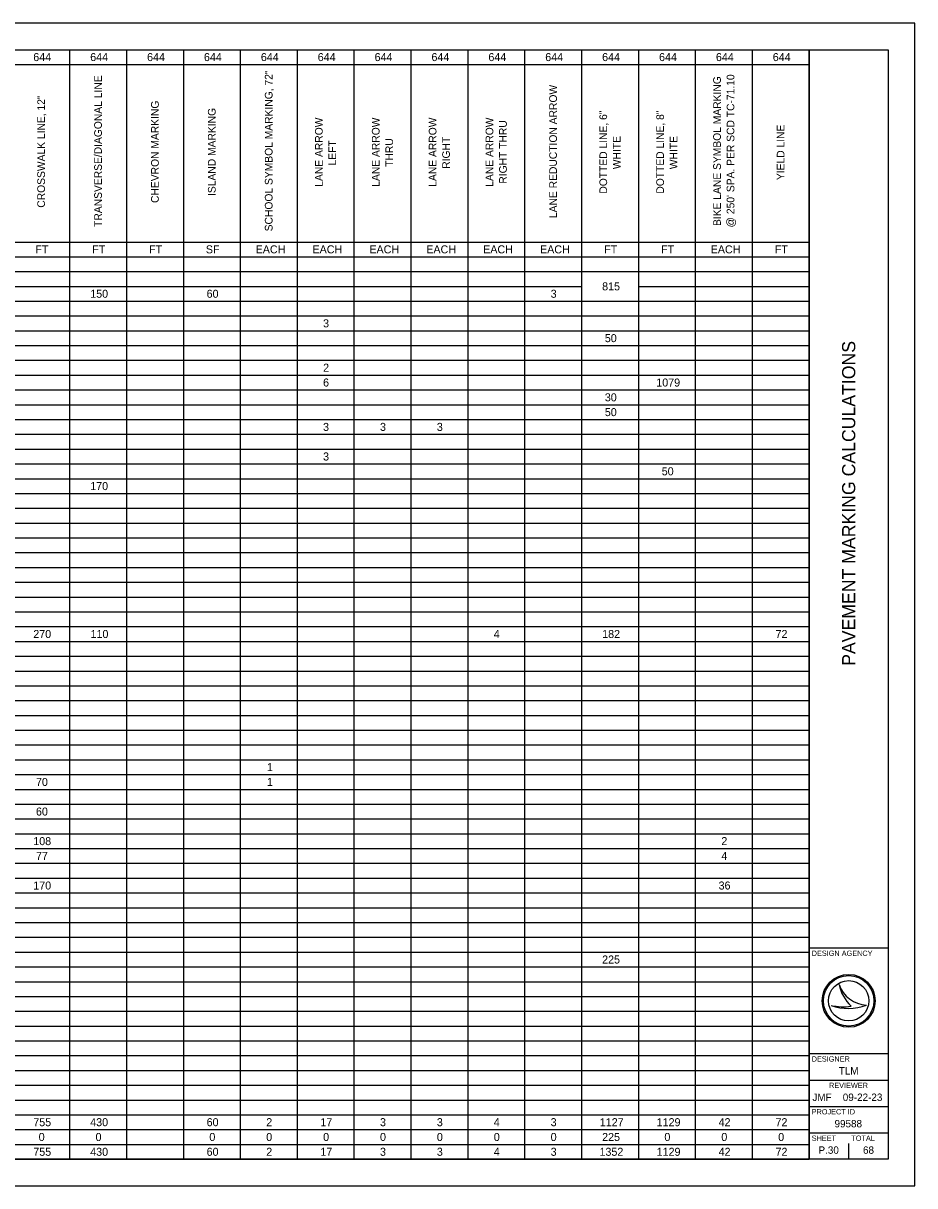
# Model space of a CAD drawing. Extents: x 0 to 34, y 0 to 22.
# Drawn here: x 17.13 to 34, y 0 to 22 of the extents above; entities that cross this region are included whole.
import ezdxf

# ---------------------------------------------------------------- set-up
doc = ezdxf.new("R2010")
doc.units = 0
for name, color, linetype in [('SH_Border', 7, 'Continuous'), ('SH_Cut_Line', 7, 'Continuous'), ('SH_Data', 7, 'Continuous'), ('SH_Text', 7, 'Continuous')]:
    doc.layers.add(name, color=color, linetype=linetype)

msp = doc.modelspace()

# ---------------------------------------------------------------- linework, layer by layer
at = {"layer": 'SH_Border'}
for p, q in [((32, 0.5), (32, 21.5)), ((32, 4.5), (33.5, 4.5)), ((32, 2.5), (33.5, 2.5)), ((32, 2), (33.5, 2)), ((32, 1.5), (33.5, 1.5)), ((32, 1), (33.5, 1))]:
    msp.add_line(p, q, dxfattribs=at)
msp.add_lwpolyline([(1.5, 21.5), (33.5, 21.5), (33.5, 0.5), (1.5, 0.5)], close=True, dxfattribs=at)
at = {"layer": 'SH_Cut_Line'}
msp.add_lwpolyline([(0, 0), (34, 0), (34, 22), (0, 22)], close=True, dxfattribs=at)
at = {"layer": 'SH_Data'}
for p, q in [((32.567, 3.81), (32.567, 3.81)), ((32.417, 3.41), (32.417, 3.41)), ((32.75, 3.5), (32.75, 3.5)), ((33.087, 3.419), (33.087, 3.419)), ((32.375, 0.675), (32.375, 0.675)), ((32.75, 0.5), (32.75, 0.8))]:
    msp.add_line(p, q, dxfattribs=at)
for radius in [0.5, 0.477, 0.477, 0.382]:
    msp.add_circle((32.75, 3.5), radius, dxfattribs=at)
for centre, radius, start, end in [((33.116, 3.998), 0.58, 198.9257, 198.9319), ((33.347, 3.97), 0.796, 191.6379, 191.6421), ((33.116, 3.998), 0.58, 198.9319, 267.1657), ((33.347, 3.97), 0.796, 191.6421, 226.0947), ((32.739, 4.37), 1.013, 251.4576, 290.0832), ((32.648, 4.654), 1.266, 259.4964, 259.4995), ((32.739, 4.37), 1.013, 251.4527, 251.4576), ((32.648, 4.654), 1.266, 259.4995, 276.6672)]:
    msp.add_arc(centre, radius, start, end, dxfattribs=at)
at = {"layer": 'SH_Text'}
for p, q in [((1.5, 21.5), (32.001, 21.5)), ((18.009, 21.5), (18.009, 0.502)), ((19.085, 21.5), (19.085, 0.502)), ((20.161, 21.5), (20.161, 0.502)), ((21.238, 21.5), (21.238, 0.502)), ((22.314, 21.5), (22.314, 0.502)), ((23.39, 21.5), (23.39, 0.502)), ((24.467, 21.5), (24.467, 0.502)), ((25.543, 21.5), (25.543, 0.502)), ((26.619, 21.5), (26.619, 0.502)), ((27.696, 21.5), (27.696, 0.502)), ((28.772, 21.5), (28.772, 0.502)), ((29.848, 21.5), (29.848, 0.502)), ((30.924, 21.5), (30.924, 0.502)), ((32.001, 21.5), (32.001, 0.502)), ((8.322, 21.22), (32.001, 21.22)), ((8.322, 17.86), (32.001, 17.86)), ((1.5, 17.58), (32.001, 17.58)), ((1.5, 17.3), (32.001, 17.3)), ((1.5, 17.021), (27.696, 17.021)), ((28.772, 17.021), (32.001, 17.021)), ((1.5, 16.741), (32.001, 16.741)), ((1.5, 16.461), (32.001, 16.461)), ((1.5, 16.181), (32.001, 16.181)), ((1.5, 15.901), (32.001, 15.901)), ((1.5, 15.621), (32.001, 15.621)), ((1.5, 15.341), (32.001, 15.341)), ((1.5, 15.061), (32.001, 15.061)), ((1.5, 14.781), (32.001, 14.781)), ((1.5, 14.501), (32.001, 14.501)), ((1.5, 14.221), (32.001, 14.221)), ((1.5, 13.941), (32.001, 13.941)), ((1.5, 13.661), (32.001, 13.661)), ((1.5, 13.381), (32.001, 13.381)), ((1.5, 13.101), (32.001, 13.101)), ((1.5, 12.821), (32.001, 12.821)), ((1.5, 12.541), (32.001, 12.541)), ((1.5, 12.261), (32.001, 12.261)), ((1.5, 11.981), (32.001, 11.981)), ((1.5, 11.701), (32.001, 11.701)), ((1.5, 11.421), (32.001, 11.421)), ((1.5, 11.141), (32.001, 11.141)), ((1.5, 10.861), (32.001, 10.861)), ((1.5, 10.581), (32.001, 10.581)), ((1.5, 10.301), (32.001, 10.301)), ((1.5, 10.021), (32.001, 10.021)), ((1.5, 9.741), (32.001, 9.741)), ((1.5, 9.461), (32.001, 9.461)), ((1.5, 9.181), (32.001, 9.181)), ((1.5, 8.901), (32.001, 8.901)), ((1.5, 8.621), (32.001, 8.621)), ((1.5, 8.342), (32.001, 8.342)), ((1.5, 8.062), (32.001, 8.062)), ((1.5, 7.782), (32.001, 7.782)), ((1.5, 7.502), (32.001, 7.502)), ((1.5, 7.222), (32.001, 7.222)), ((1.5, 6.942), (32.001, 6.942)), ((1.5, 6.662), (32.001, 6.662)), ((1.5, 6.382), (32.001, 6.382)), ((1.5, 6.102), (32.001, 6.102)), ((1.5, 5.822), (32.001, 5.822)), ((1.5, 5.542), (32.001, 5.542)), ((1.5, 5.262), (32.001, 5.262)), ((1.5, 4.982), (32.001, 4.982)), ((1.5, 4.702), (32.001, 4.702)), ((1.5, 4.422), (32.001, 4.422)), ((1.5, 4.142), (32.001, 4.142)), ((1.5, 3.862), (32.001, 3.862)), ((1.5, 3.582), (32.001, 3.582)), ((1.5, 3.302), (32.001, 3.302)), ((1.5, 3.022), (32.001, 3.022)), ((1.5, 2.742), (32.001, 2.742)), ((1.5, 2.462), (32.001, 2.462)), ((1.5, 2.182), (32.001, 2.182)), ((1.5, 1.902), (32.001, 1.902)), ((1.5, 1.622), (32.001, 1.622)), ((1.5, 1.342), (32.001, 1.342)), ((1.5, 1.062), (32.001, 1.062)), ((1.5, 0.782), (32.001, 0.782)), ((1.5, 0.502), (32.001, 0.502))]:
    msp.add_line(p, q, dxfattribs=at)

# ---------------------------------------------------------------- texts
at = {"layer": 'SH_Data'}
msp.add_text('PAVEMENT MARKING CALCULATIONS', height=0.25, rotation=90, dxfattribs=at).set_placement((32.875, 9.839))
for s, height, p in [('DESIGN AGENCY', 0.1, (32.05, 4.35)), ('DESIGNER', 0.1, (32.05, 2.35)), ('TLM', 0.14, (32.562, 2.105)), ('REVIEWER', 0.1, (32.378, 1.85)), ('JMF', 0.14, (32.064, 1.605)), ('09-22-23', 0.14, (32.638, 1.605)), ('PROJECT ID', 0.1, (32.05, 1.35)), ('99588', 0.14, (32.482, 1.105)), ('SHEET', 0.1, (32.05, 0.85)), ('TOTAL', 0.1, (32.8, 0.85)), ('P.30', 0.14, (32.179, 0.605)), ('68', 0.14, (33.021, 0.605))]:
    msp.add_text(s, height=height, dxfattribs=at).set_placement(p)
at = {"layer": 'SH_Text'}
for s, height, p in [('644', 0.1515, (17.322, 21.284)), ('644', 0.1515, (18.399, 21.284)), ('644', 0.1515, (19.475, 21.284)), ('644', 0.1515, (20.551, 21.284)), ('644', 0.1515, (21.628, 21.284)), ('644', 0.1515, (22.704, 21.284)), ('644', 0.1515, (23.78, 21.284)), ('644', 0.1515, (24.856, 21.284)), ('644', 0.1515, (25.933, 21.284)), ('644', 0.1515, (27.009, 21.284)), ('644', 0.1515, (28.085, 21.284)), ('644', 0.1515, (29.162, 21.284)), ('644', 0.1515, (30.238, 21.284)), ('644', 0.1515, (31.314, 21.284)), ('FT', 0.1515, (17.361, 17.645)), ('FT', 0.1515, (18.437, 17.645)), ('FT', 0.1515, (19.513, 17.645)), ('SF', 0.1515, (20.587, 17.645)), ('EACH', 0.1515, (21.529, 17.645)), ('EACH', 0.1515, (22.605, 17.645)), ('EACH', 0.1515, (23.681, 17.645)), ('EACH', 0.1515, (24.758, 17.645)), ('EACH', 0.1515, (25.834, 17.645)), ('EACH', 0.1515, (26.91, 17.645)), ('FT', 0.1515, (28.124, 17.645)), ('FT', 0.1515, (29.2, 17.645)), ('EACH', 0.1515, (30.139, 17.645)), ('FT', 0.1515, (31.353, 17.645)), ('150', 0.1515, (18.399, 16.805)), ('60', 0.1515, (20.602, 16.805)), ('3', 0.152, (27.111, 16.805)), ('815', 0.1515, (28.085, 16.945)), ('3', 0.152, (22.805, 16.245)), ('50', 0.1515, (28.136, 15.965)), ('2', 0.152, (22.806, 15.405)), ('6', 0.152, (22.805, 15.125)), ('1079', 0.1515, (29.11, 15.125)), ('30', 0.1515, (28.136, 14.845)), ('50', 0.1515, (28.136, 14.565)), ('3', 0.152, (22.805, 14.285)), ('3', 0.152, (23.882, 14.285)), ('3', 0.152, (24.958, 14.285)), ('3', 0.152, (22.805, 13.725)), ('50', 0.1515, (29.213, 13.445)), ('170', 0.1515, (18.399, 13.165)), ('270', 0.1515, (17.322, 10.366)), ('110', 0.1515, (18.405, 10.366)), ('4', 0.152, (26.035, 10.366)), ('182', 0.1515, (28.086, 10.366)), ('72', 0.1515, (31.366, 10.366)), ('1', 0.152, (21.742, 7.846)), ('70', 0.1515, (17.373, 7.566)), ('1', 0.152, (21.742, 7.566)), ('60', 0.1515, (17.373, 7.006)), ('108', 0.1515, (17.322, 6.446)), ('2', 0.152, (30.34, 6.446)), ('77', 0.1515, (17.373, 6.166)), ('4', 0.152, (30.34, 6.166)), ('170', 0.1515, (17.322, 5.606)), ('36', 0.1515, (30.289, 5.606)), ('225', 0.1515, (28.085, 4.206)), ('755', 0.1515, (17.322, 1.127)), ('430', 0.1515, (18.399, 1.127)), ('60', 0.1515, (20.602, 1.127)), ('2', 0.152, (21.73, 1.127)), ('17', 0.1515, (22.754, 1.127)), ('3', 0.152, (23.882, 1.127)), ('3', 0.152, (24.958, 1.127)), ('4', 0.152, (26.035, 1.127)), ('3', 0.152, (27.111, 1.127)), ('1127', 0.1515, (28.041, 1.127)), ('1129', 0.1515, (29.117, 1.127)), ('42', 0.1515, (30.289, 1.127)), ('72', 0.1515, (31.366, 1.127)), ('0', 0.152, (17.424, 0.847)), ('0', 0.152, (18.5, 0.847)), ('0', 0.152, (20.653, 0.847)), ('0', 0.152, (21.729, 0.847)), ('0', 0.152, (22.806, 0.847)), ('0', 0.152, (23.882, 0.847)), ('0', 0.152, (24.958, 0.847)), ('0', 0.152, (26.035, 0.847)), ('0', 0.152, (27.111, 0.847)), ('225', 0.1515, (28.085, 0.847)), ('0', 0.152, (29.263, 0.847)), ('0', 0.152, (30.34, 0.847)), ('0', 0.152, (31.416, 0.847)), ('755', 0.1515, (17.322, 0.567)), ('430', 0.1515, (18.399, 0.567)), ('60', 0.1515, (20.602, 0.567)), ('2', 0.152, (21.73, 0.567)), ('17', 0.1515, (22.754, 0.567)), ('3', 0.152, (23.882, 0.567)), ('3', 0.152, (24.958, 0.567)), ('4', 0.152, (26.035, 0.567)), ('3', 0.152, (27.111, 0.567)), ('1352', 0.1515, (28.035, 0.567)), ('1129', 0.1515, (29.117, 0.567)), ('42', 0.1515, (30.289, 0.567)), ('72', 0.1515, (31.366, 0.567))]:
    msp.add_text(s, height=height, dxfattribs=at).set_placement(p)
for s, height, p in [('TRANSVERSE/DIAGONAL LINE', 0.14562, (18.62, 18.146)), ('SCHOOL SYMBOL MARKING, 72"', 0.14562, (21.849, 18.062)), ('BIKE LANE SYMBOL MARKING', 0.14562, (30.332, 18.163)), ("@ 250' SPA. PER SCD TC-71.10", 0.14562, (30.587, 18.136)), ('LANE REDUCTION ARROW', 0.14562, (27.23, 18.313)), ('CROSSWALK LINE, 12"', 0.14562, (17.543, 18.509)), ('CHEVRON MARKING', 0.14562, (19.696, 18.599)), ('ISLAND MARKING', 0.14562, (20.772, 18.731)), ('DOTTED LINE, 6"', 0.14562, (28.179, 18.775)), ('DOTTED LINE, 8"', 0.14562, (29.255, 18.775)), ('LANE ARROW', 0.1456, (22.798, 18.906)), ('LANE ARROW', 0.1456, (23.874, 18.906)), ('LANE ARROW', 0.1456, (24.95, 18.906)), ('LANE ARROW', 0.1456, (26.026, 18.906)), ('RIGHT THRU', 0.1456, (26.281, 18.964)), ('YIELD LINE', 0.1456, (31.535, 19.032)), ('THRU', 0.1456, (24.129, 19.283)), ('RIGHT', 0.1456, (25.205, 19.246)), ('WHITE', 0.1456, (28.434, 19.238)), ('WHITE', 0.1456, (29.51, 19.238)), ('LEFT', 0.1456, (23.052, 19.309))]:
    msp.add_text(s, height=height, rotation=90, dxfattribs=at).set_placement(p)

doc.saveas('drawing.dxf')
